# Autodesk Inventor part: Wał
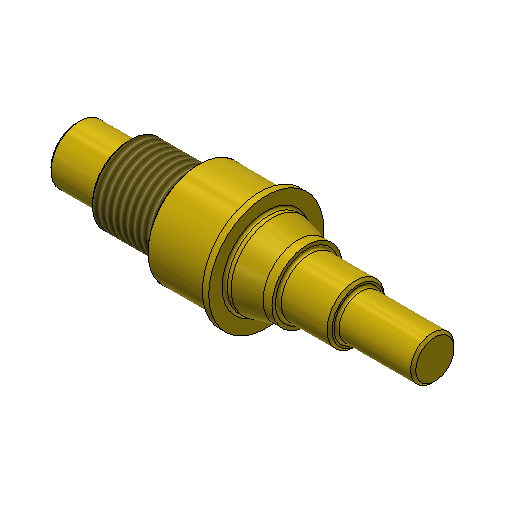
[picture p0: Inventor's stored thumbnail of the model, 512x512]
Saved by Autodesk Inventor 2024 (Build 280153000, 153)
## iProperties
Company: ATC
CustomPartVersion: 1
Created: 2023-03
Part Number: Wał
Material: Stal kuta
Document SubType Name: Modeling
Designer: Andrzej Jaskulski
Density: 1 g/cm^3
Appearance: Lśniąca — złota
Checked By: A.J.
Engr Approved By: Andrzej Jaskulski
Mfg Approved By: Andrzej Jaskulski
Authority: A.J.
Length: 280,000 mm
Title: A.J.: Kurs R2024-MEP
Author: Andrzej Jaskulski
Revision Number: 1/24
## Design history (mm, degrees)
sketch "Szkic główny"
  geometry: L1 (0, 0)-(280, 0) reference; L2 (0, 0)-(0, 22.5); L3 (0, 22.5)-(40, 22.5); L4 (40, 22.5)-(40, 30); L5 (90, 30)-(90, 27.5); L6 (40, 30)-(90, 30); L7 (90, 27.5)-(95, 27.5); L8 (95, 27.5)-(95, 40); L9 (95, 40)-(143, 40); L10 (143, 40)-(143, 45); L11 (148, 45)-(148, 32.5); L12 (143, 45)-(148, 45); L13 (148, 32.5)-(153, 32.5); L14 (153, 32.5)-(173, 27.5); L15 (180, 27.5)-(180, 22.5); L16 (173, 27.5)-(180, 27.5); L17 (220, 22.5)-(220, 17); L18 (180, 22.5)-(220, 22.5); L19 (280, 17)-(280, 0); L20 (220, 17)-(280, 17)
  constraints: 40 end point, 11 horizontal, 9 vertical
revolve "Obrót1" sketch "Szkic główny" stored, may be unused: angle "d6" = 0 deg
chamfer "Faza12" distance "d56" = 2; stored, may be unused: second distance "d57" = 0.125, angle "d58" = 45 deg
fillet "Zaokrąglenie7" dims "d59" = 2
chamfer "Faza13" distance "d60" = 2; stored, may be unused: second distance "d61" = 0.125, angle "d62" = 45 deg
feature "Gwint3" dims "d63" = 50, "d64" = 0
chamfer "Faza14" distance "d65" = 2; stored, may be unused: second distance "d66" = 2, angle "d67" = 45 deg
fillet "Zaokrąglenie8" dims "d68" = 0.5
fillet "Zaokrąglenie9" dims "d69" = 0.5
chamfer "Faza15" distance "d70" = 0.5; stored, may be unused: second distance "d71" = 0.125, angle "d72" = 45 deg
node "Podcięcie4"
fillet "Zaokrąglenie10" dims "d73" = 2
node "Podcięcie5"
chamfer "Faza16" distance "d74" = 2; stored, may be unused: second distance "d75" = 0.125, angle "d76" = 45 deg
fillet "Zaokrąglenie11" dims "d77" = 2
chamfer "Faza17" distance "d78" = 2; stored, may be unused: second distance "d79" = 0.125, angle "d80" = 45 deg
node "Bryła1"
node "Korpusy bryłowe"
node "Korpusy powierzchniowe"
feature "iFeature1:3"
feature "iFeature1:4"
other parameters: "d0" = 0, "d1" = 0, "d2" = 0, "Length" = 280 [user parameter]
